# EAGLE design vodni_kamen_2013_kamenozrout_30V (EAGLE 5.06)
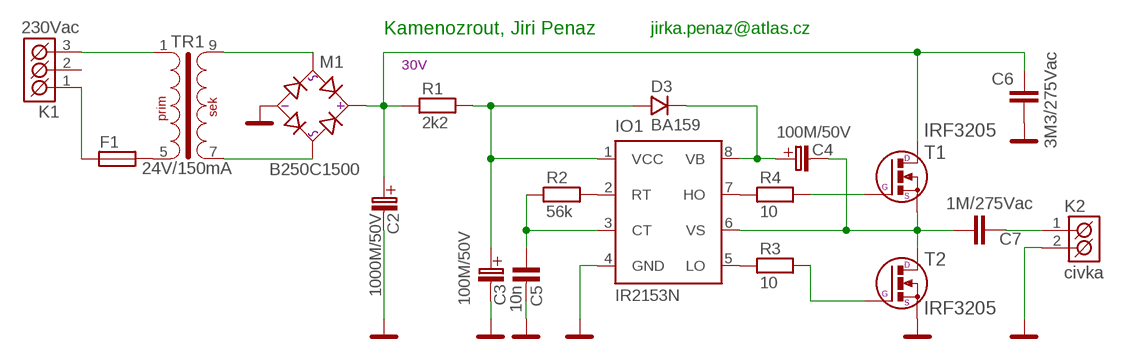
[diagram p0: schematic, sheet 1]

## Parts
C2  1000M/50V  [C_EL_7,5]
C3  100M/50V  [C_EL_3,5]
C4  100M/50V  [C_EL_3,5]
C5  10n  C-KERAMIK_5  [C-5]
C6  3M3/275Vac  C27/11  [C27.5B11]
C7  1M/275Vac  C27/11  [C27.5B11]
D3  BA159  [DO41]
F1  FUSEKS20  [FUSE_KS20]
IO1  IR2153N  [DIP8]
K1  230Vac  ARK500/3  [ARK500/3]
K2  civka  ARK500/2  [ARK500/2]
M1  B250C1500  D-MUSTEK_B250C1500  [DM_WOM]
R1  2k2  R_7,5  [R-7,5]
R2  56k  R_7,5  [R-7,5]
R3  10  R_7,5  [R-7,5]
R4  10  R_7,5  [R-7,5]
T1  IRF3205  BUZ11_LEZ  [TO-220]
T2  IRF3205  BUZ11_LEZ  [TO-220]
TR1  24V/150mA  TRHEI382-1  [TRHEI382]

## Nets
+30V: C2.C+(C_EL+) C6.1 M1.+ R1.1 T1.2(D)
GND: C2.C-(C_EL-) C3.C-(C_EL-) C5.2 C6.2 IO1.4(GND) K2.2(K2) M1.- T2.3(S)
N$1: IO1.7(HO) R4.1
N$2: IO1.2(RT) R2.2
N$3: C5.1 IO1.3(CT) R2.1
N$4: IO1.5(LO) R3.1
N$5: R3.2 T2.1(G)
N$6: R4.2 T1.1(G)
N$7: C4.C-(C_EL-) C7.1 IO1.6(VS) T1.3(S) T2.2(D)
N$8: C4.C+(C_EL+) D3.K IO1.8(VB)
N$9: C3.C+(C_EL+) D3.A IO1.1(VCC) R1.2
N$10: K1.3(K3) TR1.1
N$11: M1.AC2 TR1.9(S2)
N$13: F1.1 K1.1(K1)
N$14: M1.AC1 TR1.7(S1)
N$15: C7.2 K2.1(K1)
N$18: F1.2 TR1.5(P2)
Unconnected: K1.2(K2)

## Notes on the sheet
- Kamenozrout, Jiri Penaz | jirka.penaz@atlas.cz
- 30V

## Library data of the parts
C2 = #PaJa_C-el_2:1000M/50V
C3 C4 = #PaJa_C-el_2:100M/50V
C5 = #PaJa_31:C-KERAMIK: Kondenzator - keramicky
C6 C7 = capacitor-wima:C: CAPACITOR
D3 = #PaJa_31:BA159: Rychlá dioda - 1A, 1000V
F1 = #PaJa_32:FUSE: Pojistkove pouzdro
IO1 = Jan16:IR2153: IR2153 is a halfbridge driver with internal oscillator simillar to 555.
K1 = #PaJa_konektory:ARK500/3: Svorkovnice - roztec 5mm - trojita
K2 = #PaJa_konektory:ARK500/2: Svorkovnice - roztec 5mm - dvojita
M1 = #PaJa_31:D-MUSTEK: Diodovy mustek - Graetz
R1-R4 = #PaJa_31:R: Rezistor
T1 T2 = #PaJa_31:BUZ11: N-Channel Enhancement MOSFET 50V; 20A; 0,080Ohm
TR1 = #PaJa_31:TRHEI382-1: Transformator - do DPS - 4,5 VA

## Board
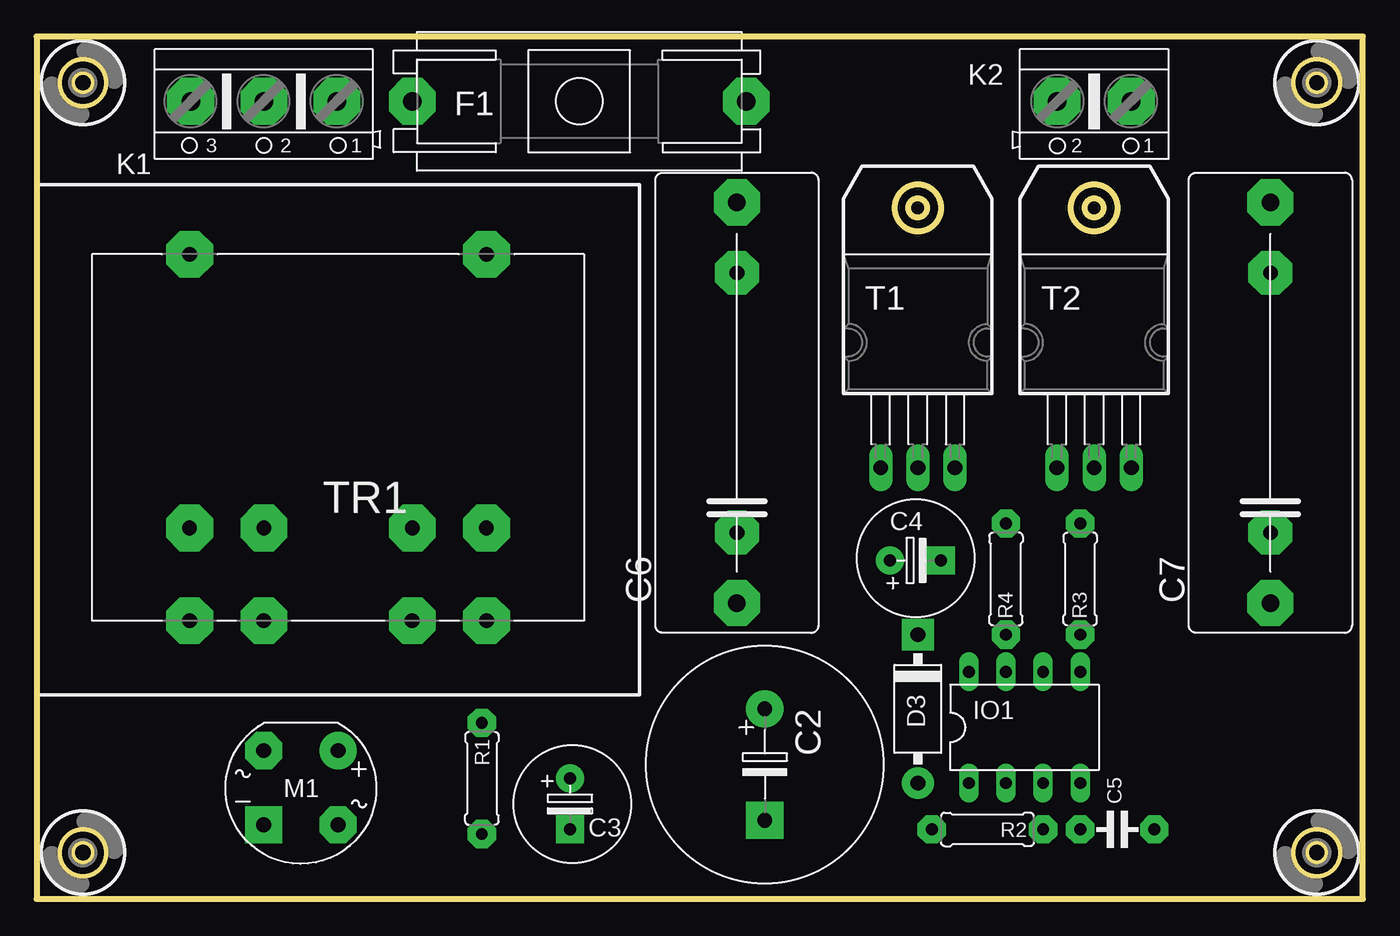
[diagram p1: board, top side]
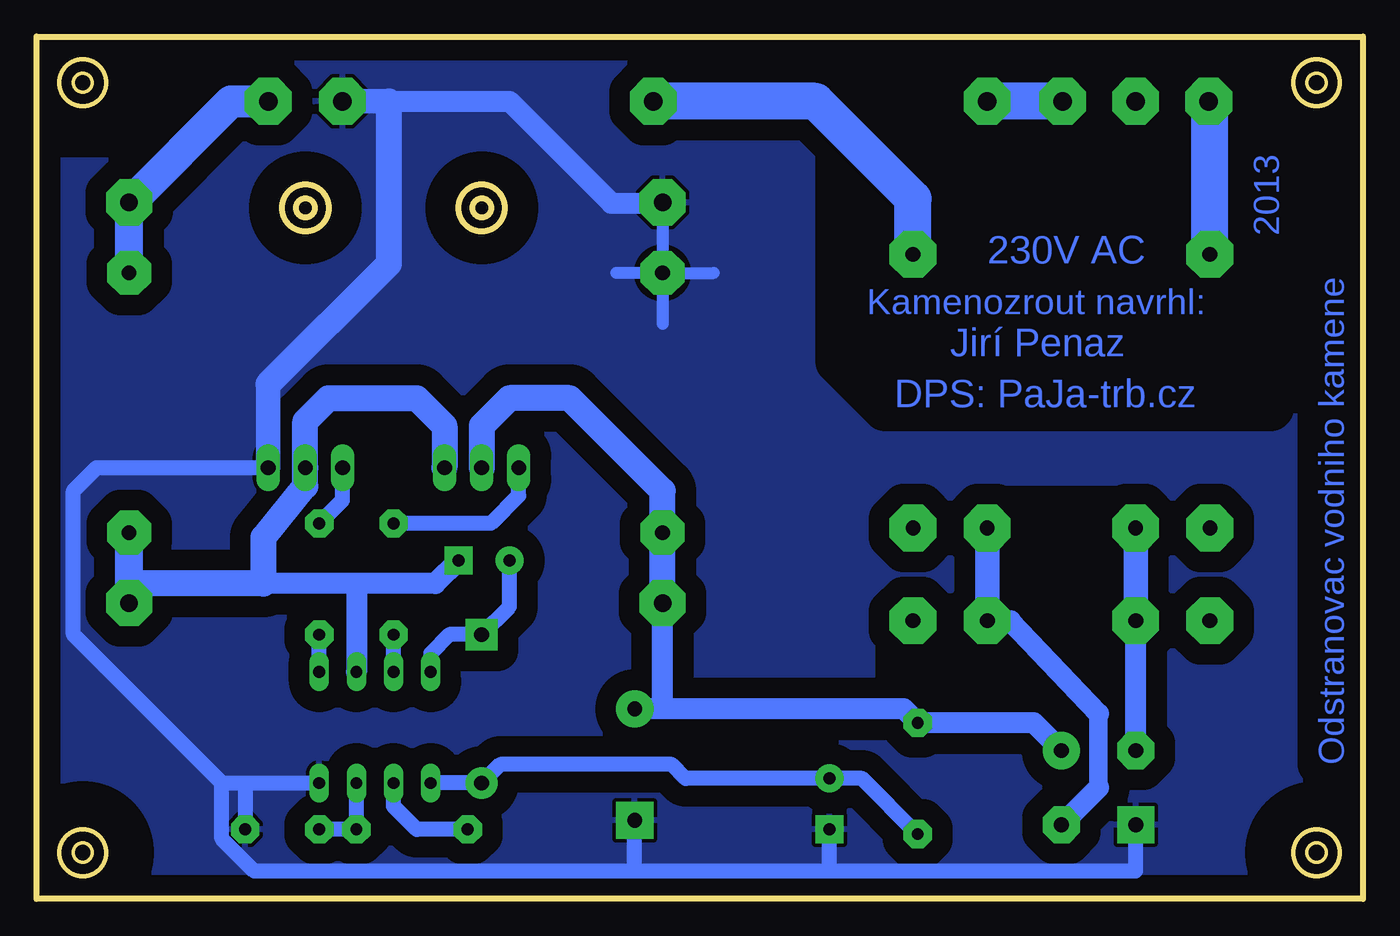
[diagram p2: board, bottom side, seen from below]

Size 90.79 x 59.05 mm. Coordinates in mm from the lower left corner, seen from the top.
Outline: 0,0 90.79,0 90.79,59.05 0,59.05 0,0
Outline: circle at 60.33,47.31 radius 0.64
Outline: circle at 72.39,47.31 radius 0.64
Outline: circle at 60.33,47.31 radius 1.59
Outline: circle at 72.39,47.31 radius 1.59
Copper layers (1*16): Top 0.035mm / dielectric 1.5mm / Bottom 0.035mm
Design rules "default": minimum track width 10mil, minimum drill 24mil, track to track 8mil, track to pad 8mil, pad to pad 8mil, via to via 8mil, smd to smd 8mil, copper to edge 40mil, drill to drill 8mil, minimum pad ring 10mil, minimum via ring 8mil, stop-mask expansion 4mil, vias tented up to drill 0mil, thermal gap 10mil
bRestrict: area 47.6,42.5 to 48.3,43.2; area 70.5,45.4 to 74.3,49.2; area 58.4,45.4 to 62.2,49.2; area 58.1,45.1 to 62.5,49.5; area 70.2,45.1 to 74.6,49.5; 6 lines

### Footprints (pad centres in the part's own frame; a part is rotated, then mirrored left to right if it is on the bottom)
C_EL_7,5 = drill 1.016 pad 2.54 round: C+ -3.81,0 | drill 1.016 pad 2.54 square: C- 3.81,0
C_EL_3,5 = drill 0.813 pad 1.93 round: C+ 0,0 | drill 0.813 pad 1.93 square: C- 3.493,0
C-5 = drill 0.813 pad 1.93 octagon: 1 -2.54,0; 2 2.54,0
C27.5B11 = drill 1.194 pad 3.15 octagon: 1 -13.716,0; 2 13.716,0
DO41 = drill 1.016 pad 2.184 round: A -5.08,0 | drill 1.016 pad 2.184 square: K 5.08,0
FUSE_KS20 = drill 1.27 pad 3.2 octagon: 1 -11.43,0; 2 11.43,0
DIP8 = drill 0.813 long: 1 -3.81,-3.81; 2 -1.27,-3.81; 3 1.27,-3.81; 4 3.81,-3.81; 5 3.81,3.81; 6 1.27,3.81; 7 -1.27,3.81; 8 -3.81,3.81
ARK500/3 = drill 1.27 pad 3.2 octagon: 1 -5,0; 2 0,0; 3 5,0
ARK500/2 = drill 1.27 pad 3.2 octagon: 1 -2.54,0; 2 2.54,0
DM_WOM = drill 1.016 pad 2.54 round: + -2.54,-2.54 | drill 1.016 pad 2.54 square: - 2.54,2.54 | drill 1.016 pad 2.54 octagon: AC1 -2.54,2.54; AC2 2.54,-2.54
R-7,5 = drill 0.813 pad 1.93 octagon: 1 -3.81,0; 2 3.81,0
TO-220 = drill 1.016 pad 1.6 long: 1 -2.54,0; 2 0,0; 3 2.54,0
TRHEI382 = drill 1.016 pad 3.2 octagon: 1 -10.16,12.7; 5 10.16,12.7; 6 10.16,-12.383; 7 5.08,-12.383; 9 -5.08,-12.383; 10 -10.16,-12.383
HOLE_3,0 = hole 3.2: 0,0

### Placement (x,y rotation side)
C2  49.85,9.21 270 top
C3  36.51,8.25 270 top
C4  58.42,23.18 0 top
C5  73.98,4.76 0 top
C6  47.94,33.97 90 top
C7  84.45,33.97 90 top
D3  60.33,13.02 90 top
F1  37.15,54.61 0 top
IO1  67.63,11.75 0 top
K1  15.56,54.61 180 top
K2  72.39,54.61 180 top
M1  18.1,7.62 180 top
R1  30.48,8.25 270 top
R2  65.09,4.76 180 top
R3  71.44,21.91 90 top
R4  66.36,21.91 90 top
T1  60.33,29.53 0 top
T2  72.39,29.53 0 top
TR1  20.64,31.43 0 top
U$1  [HOLE_3,0]  3.17,3.17 0 top
U$2  [HOLE_3,0]  87.63,3.17 0 top
U$3  [HOLE_3,0]  87.63,55.88 0 top
U$4  [HOLE_3,0]  3.17,55.88 0 top

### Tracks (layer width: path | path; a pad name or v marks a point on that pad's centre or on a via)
+30V  (via drill 1 pad 3)
  Bottom 1.422: 47.94,13.02 C6.1 | 47.94,13.02 C2.C+ | M1.+ 22.54,12.07 R1.1 31.43,13.02 47.94,13.02
  Bottom 1.778: C6.1 v47.94,25.08 47.94,27.94 54.29,34.29 58.42,34.29 60.33,32.38 T1.2
GND  (via drill 1 pad 3)
  Bottom 0.813: v47.94,42.86 47.94,47.62 C6.2 | v47.94,42.86 47.94,39.37 | v47.94,42.86 51.12,42.86 | v47.94,42.86 44.45,42.86
  Bottom 1.016: 78.11,7.94 78.11,4.13 75.88,1.91 49.85,1.91 | 78.11,7.94 76.52,7.94 | 76.52,7.94 IO1.4 | 76.52,7.94 C5.2 | 36.51,1.91 15.56,1.91 M1.- | 36.51,1.91 49.85,1.91 | 36.51,1.91 C3.C- | 49.85,1.91 C2.C- | 78.11,7.94 88.27,18.1 88.27,27.94 86.68,29.53 T2.3
  Bottom 1.422: 66.67,54.61 58.42,54.61 51.44,47.62 47.94,47.62
  Bottom 1.676: 66.67,54.61 K2.2 | T2.3 74.93,35.24
  Bottom 1.778: 74.93,35.24 66.67,43.5 66.67,54.61
  pour Bottom (isolate 1.422): 0,0 0,59.05 90.81,59.05 90.81,0
N$1
  Bottom 1.016: IO1.7 R4.1
N$2
  Bottom 1.016: R2.2 64.77,4.76 66.36,6.35 IO1.2
N$3
  Bottom 1.016: IO1.3 R2.1 C5.1
N$4
  Bottom 1.016: IO1.5 R3.1
N$5
  Bottom 1.016: R3.2 69.85,27.3 T2.1
N$6
  Bottom 1.016: T1.1 57.78,27.62 59.69,25.72 R4.2
N$7  (via drill 1 pad 3)
  Bottom 1.422: 68.9,21.59 75.25,21.59 | 68.9,21.59 IO1.6 | C4.C- 63.5,21.59 68.9,21.59 | 84.39,21.59 C7.1
  Bottom 1.778: T1.3 62.87,32.38 64.77,34.29 70.8,34.29 72.39,32.7 T2.2 72.39,28.26 75.25,24.77 75.25,21.59 84.39,21.59
  Bottom 1.93: C7.1 v84.45,25.08
N$8
  Bottom 1.016: C4.C+ 58.42,20 D3.K 62.55,18.1 63.82,16.83 IO1.8
N$9
  Bottom 1.016: IO1.1 D3.A 59.05,9.21 47.31,9.21 46.35,8.25 C3.C+ 34.29,8.25 R1.2
N$10
  Bottom 2.54: TR1.1 10.48,54.53 K1.3
N$11  (via drill 1 pad 3.2)
  Bottom 1.422: M1.AC2 TR1.9
  Bottom 1.676: TR1.9 v15.56,25.4
N$12  (via drill 1 pad 3.2)
  other vias: 10.48,25.4
N$13
  Bottom 2.54: K1.1 F1.1
N$14  (via drill 1 pad 3.2)
  Bottom 1.27: 18.1,7.62 18.1,12.7 | 24.13,19.05 TR1.7
  Bottom 1.422: M1.AC1 18.1,7.62 | 18.1,12.7 24.13,19.05
  Bottom 1.676: TR1.7 v25.72,25.4
N$15  (via drill 1 pad 3)
  Bottom 1.93: v84.45,42.86 C7.2
  Bottom 2.184: C7.2 84.39,47.69 77.47,54.61 K2.1
N$17  (via drill 1 pad 3.2)
  other vias: 30.8,25.4
N$18
  Bottom 2.54: F1.2 37.47,54.61 30.8,47.94 TR1.5

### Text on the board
Bottom: 2013 | 230V AC | Kamenozrout navrhl: | Jirí Penaz | DPS: PaJa-trb.cz | Odstranovac vodniho kamene
PaJa: www.paja-trb.cz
